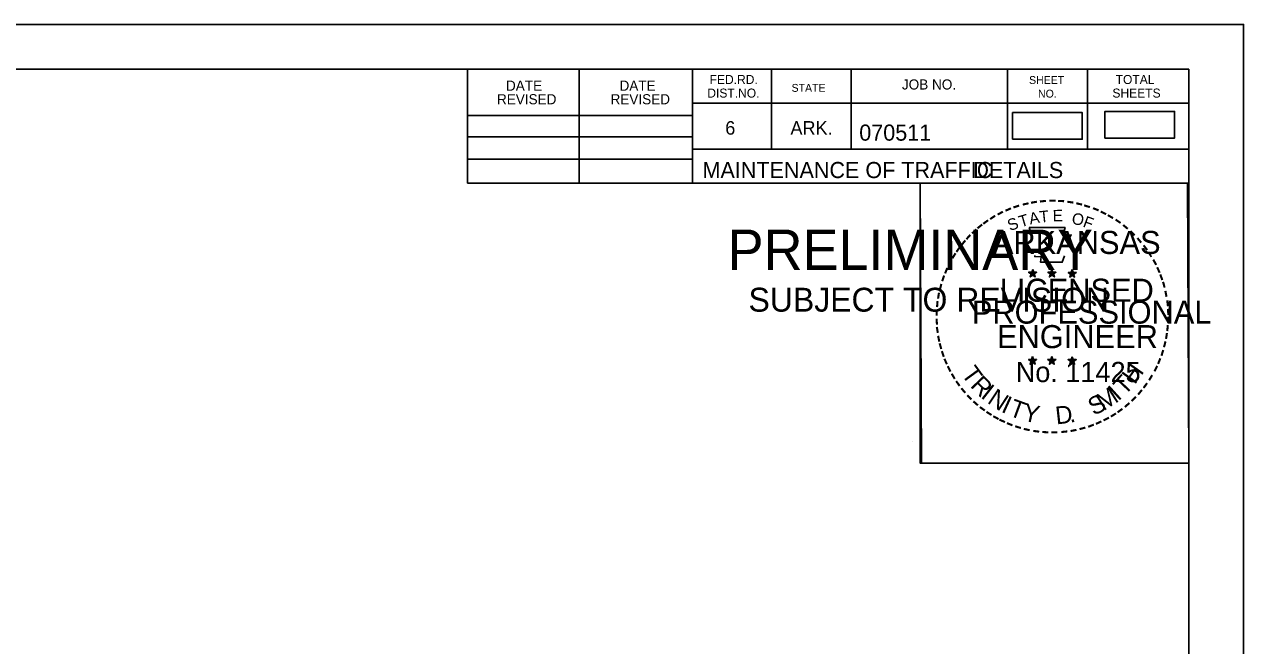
# Model space of a CAD drawing. Extents: x 1398460 to 1408037, y 380768 to 383968.
# Drawn here: x 1403470 to 1403999, y 383698 to 383968 of the extents above; entities that cross this region are included whole.
import ezdxf

# ---------------------------------------------------------------- set-up
doc = ezdxf.new("R2010")
doc.units = 0
for name, color, linetype in [('R_Border', 7, 'Continuous'), ('R_Border PE', 7, 'Continuous'), ('R_Border Prem', 7, 'Continuous'), ('R_Dimension', 7, 'Continuous'), ('R_No Plot', 7, 'Continuous')]:
    doc.layers.add(name, color=color, linetype=linetype)

msp = doc.modelspace()

# ---------------------------------------------------------------- linework, layer by layer
at = {"layer": 'R_Border'}
for p, q in [((1402394.27, 383948.11), (1403975.17, 383948.11)), ((1403661.97, 383898.71), (1403661.97, 383948.11)), ((1403710.37, 383898.71), (1403710.37, 383948.11)), ((1403759.67, 383948.11), (1403759.67, 383898.71)), ((1403793.87, 383948.11), (1403793.87, 383913.41)), ((1403828.57, 383948.11), (1403828.57, 383913.41)), ((1403896.47, 383948.11), (1403896.47, 383913.41)), ((1403931.17, 383948.11), (1403931.17, 383913.41)), ((1403975.17, 382920.81), (1403975.17, 383948.11)), ((1403975.17, 383933.41), (1403759.67, 383933.41)), ((1403975.17, 383933.51), (1403975.17, 383933.51)), ((1403661.97, 383928.01), (1403759.67, 383928.01)), ((1403661.97, 383918.71), (1403759.67, 383918.71)), ((1403661.97, 383909.01), (1403759.67, 383909.01)), ((1403975.17, 383913.41), (1403759.67, 383913.41)), ((1403774.47, 383913.41), (1403975.17, 383913.41)), ((1403975.17, 383898.71), (1403661.97, 383898.71))]:
    msp.add_line(p, q, dxfattribs=at)
at = {"layer": 'R_Border PE'}
for p, q in [((1403907.34, 383861.25), (1403907.13, 383859.99)), ((1403907.34, 383859.43), (1403907.34, 383861.25)), ((1403907.34, 383861.25), (1403907.58, 383860)), ((1403915.69, 383861.25), (1403915.48, 383859.99)), ((1403915.69, 383859.43), (1403915.69, 383861.25)), ((1403915.69, 383861.25), (1403915.93, 383860)), ((1403924.51, 383861.19), (1403924.3, 383859.93)), ((1403924.51, 383859.37), (1403924.51, 383861.19)), ((1403924.51, 383861.19), (1403924.75, 383859.94)), ((1403905.59, 383859.98), (1403907.34, 383859.43)), ((1403905.59, 383859.98), (1403906.86, 383859.76)), ((1403905.59, 383859.98), (1403906.78, 383859.37)), ((1403906.26, 383857.94), (1403907.34, 383859.43)), ((1403906.26, 383857.94), (1403906.89, 383859.16)), ((1403906.26, 383857.94), (1403907.33, 383859.03)), ((1403908.4, 383857.94), (1403907.33, 383859.01)), ((1403909.07, 383859.98), (1403907.34, 383859.43)), ((1403908.4, 383857.94), (1403907.34, 383859.43)), ((1403909.07, 383859.98), (1403907.64, 383859.74)), ((1403908.4, 383857.94), (1403907.72, 383859.4)), ((1403909.07, 383859.98), (1403908.05, 383859.47)), ((1403913.94, 383859.98), (1403915.69, 383859.43)), ((1403913.94, 383859.98), (1403915.21, 383859.76)), ((1403913.94, 383859.98), (1403915.13, 383859.37)), ((1403914.61, 383857.94), (1403915.69, 383859.43)), ((1403914.61, 383857.94), (1403915.24, 383859.16)), ((1403914.61, 383857.94), (1403915.68, 383859.03)), ((1403916.75, 383857.94), (1403915.68, 383859.01)), ((1403917.42, 383859.98), (1403915.69, 383859.43)), ((1403916.75, 383857.94), (1403915.69, 383859.43)), ((1403917.42, 383859.98), (1403915.99, 383859.74)), ((1403916.75, 383857.94), (1403916.07, 383859.4)), ((1403917.42, 383859.98), (1403916.4, 383859.47)), ((1403922.76, 383859.92), (1403924.51, 383859.37)), ((1403922.76, 383859.92), (1403924.03, 383859.7)), ((1403922.76, 383859.92), (1403923.95, 383859.31)), ((1403923.43, 383857.88), (1403924.51, 383859.37)), ((1403923.43, 383857.88), (1403924.06, 383859.1)), ((1403923.43, 383857.88), (1403924.5, 383858.97)), ((1403925.57, 383857.88), (1403924.5, 383858.95)), ((1403926.24, 383859.92), (1403924.51, 383859.37)), ((1403925.57, 383857.88), (1403924.51, 383859.37)), ((1403926.24, 383859.92), (1403924.81, 383859.68)), ((1403925.57, 383857.88), (1403924.89, 383859.34)), ((1403926.24, 383859.92), (1403925.22, 383859.41)), ((1403905.57, 383822.12), (1403907.32, 383821.56)), ((1403905.57, 383822.12), (1403906.84, 383821.89)), ((1403905.57, 383822.12), (1403906.76, 383821.51)), ((1403906.24, 383820.08), (1403907.32, 383821.56)), ((1403906.24, 383820.08), (1403906.87, 383821.3)), ((1403906.24, 383820.08), (1403907.31, 383821.16)), ((1403907.32, 383823.39), (1403907.11, 383822.13)), ((1403908.38, 383820.08), (1403907.31, 383821.15)), ((1403907.32, 383821.56), (1403907.32, 383823.39)), ((1403907.32, 383823.39), (1403907.56, 383822.14)), ((1403909.05, 383822.12), (1403907.32, 383821.56)), ((1403908.38, 383820.08), (1403907.32, 383821.56)), ((1403909.05, 383822.12), (1403907.62, 383821.87)), ((1403908.38, 383820.08), (1403907.7, 383821.53)), ((1403909.05, 383822.12), (1403908.03, 383821.61)), ((1403913.92, 383822.12), (1403915.66, 383821.56)), ((1403913.92, 383822.12), (1403915.18, 383821.89)), ((1403913.92, 383822.12), (1403915.1, 383821.51)), ((1403914.58, 383820.08), (1403915.66, 383821.56)), ((1403914.58, 383820.08), (1403915.21, 383821.3)), ((1403914.58, 383820.08), (1403915.65, 383821.16)), ((1403915.66, 383823.39), (1403915.46, 383822.13)), ((1403916.73, 383820.08), (1403915.65, 383821.15)), ((1403915.66, 383821.56), (1403915.66, 383823.39)), ((1403915.66, 383823.39), (1403915.91, 383822.14)), ((1403917.4, 383822.12), (1403915.66, 383821.56)), ((1403916.73, 383820.08), (1403915.66, 383821.56)), ((1403917.4, 383822.12), (1403915.97, 383821.87)), ((1403916.73, 383820.08), (1403916.04, 383821.53)), ((1403917.4, 383822.12), (1403916.38, 383821.61)), ((1403922.75, 383822.07), (1403924.5, 383821.51)), ((1403922.75, 383822.07), (1403924.02, 383821.84)), ((1403922.75, 383822.07), (1403923.94, 383821.46)), ((1403923.42, 383820.03), (1403924.5, 383821.51)), ((1403923.42, 383820.03), (1403924.05, 383821.25)), ((1403923.42, 383820.03), (1403924.49, 383821.11)), ((1403924.5, 383823.34), (1403924.29, 383822.08)), ((1403925.56, 383820.03), (1403924.49, 383821.1)), ((1403924.5, 383821.51), (1403924.5, 383823.34)), ((1403924.5, 383823.34), (1403924.74, 383822.09)), ((1403926.23, 383822.07), (1403924.5, 383821.51)), ((1403925.56, 383820.03), (1403924.5, 383821.51)), ((1403926.23, 383822.07), (1403924.8, 383821.82)), ((1403925.56, 383820.03), (1403924.88, 383821.48)), ((1403926.23, 383822.07), (1403925.21, 383821.56))]:
    msp.add_line(p, q, dxfattribs=at)
for points in [[(1403905.8, 383879.37), (1403907.14, 383875.24)], [(1403923.35, 383874.76), (1403924.06, 383876.18), (1403920.64, 383876.06), (1403921.38, 383879.37), (1403905.8, 383879.37)], [(1403908.26, 383867.26), (1403908.26, 383866.82), (1403911.07, 383866.73), (1403910.8, 383864.36), (1403920.15, 383864.36), (1403921.16, 383867.04)], [(1403907.34, 383861.25), (1403908.4, 383857.94), (1403905.59, 383859.98), (1403909.07, 383859.98), (1403906.26, 383857.94), (1403907.34, 383861.25)], [(1403915.69, 383861.25), (1403916.75, 383857.94), (1403913.94, 383859.98), (1403917.42, 383859.98), (1403914.61, 383857.94), (1403915.69, 383861.25)], [(1403924.51, 383861.19), (1403925.57, 383857.88), (1403922.76, 383859.92), (1403926.24, 383859.92), (1403923.43, 383857.88), (1403924.51, 383861.19)], [(1403907.32, 383823.39), (1403908.38, 383820.08), (1403905.57, 383822.12), (1403909.05, 383822.12), (1403906.24, 383820.08), (1403907.32, 383823.39)], [(1403915.66, 383823.39), (1403916.73, 383820.08), (1403913.92, 383822.12), (1403917.4, 383822.12), (1403914.58, 383820.08), (1403915.66, 383823.39)], [(1403924.5, 383823.34), (1403925.56, 383820.03), (1403922.75, 383822.07), (1403926.23, 383822.07), (1403923.42, 383820.03), (1403924.5, 383823.34)]]:
    msp.add_lwpolyline(points, dxfattribs=at)
for centre, radius in [((1403907.33, 383859.42), 0.861), ((1403907.33, 383859.42), 0.723), ((1403907.33, 383859.42), 0.579), ((1403907.33, 383859.42), 0.495), ((1403907.33, 383859.42), 0.374), ((1403907.33, 383859.42), 0.248), ((1403907.33, 383859.42), 0.148), ((1403915.68, 383859.42), 0.861), ((1403915.68, 383859.42), 0.723), ((1403915.68, 383859.42), 0.579), ((1403915.68, 383859.42), 0.495), ((1403915.68, 383859.42), 0.374), ((1403915.68, 383859.42), 0.248), ((1403915.68, 383859.42), 0.148), ((1403924.5, 383859.36), 0.861), ((1403924.5, 383859.36), 0.723), ((1403924.5, 383859.36), 0.579), ((1403924.5, 383859.36), 0.495), ((1403924.5, 383859.36), 0.374), ((1403924.5, 383859.36), 0.248), ((1403924.5, 383859.36), 0.148), ((1403907.31, 383821.56), 0.861), ((1403907.31, 383821.56), 0.723), ((1403907.31, 383821.56), 0.579), ((1403907.31, 383821.56), 0.495), ((1403907.31, 383821.56), 0.374), ((1403907.31, 383821.56), 0.248), ((1403907.31, 383821.56), 0.148), ((1403915.66, 383821.56), 0.861), ((1403915.66, 383821.56), 0.723), ((1403915.66, 383821.56), 0.579), ((1403915.66, 383821.56), 0.495), ((1403915.66, 383821.56), 0.374), ((1403915.66, 383821.56), 0.248), ((1403915.66, 383821.56), 0.148), ((1403924.49, 383821.51), 0.861), ((1403924.49, 383821.51), 0.723), ((1403924.49, 383821.51), 0.579), ((1403924.49, 383821.51), 0.495), ((1403924.49, 383821.51), 0.374), ((1403924.49, 383821.51), 0.248), ((1403924.49, 383821.51), 0.148)]:
    msp.add_circle(centre, radius, dxfattribs=at)
at = {"layer": 'R_Dimension'}
for points in [[(1403898.59, 383917.72), (1403928.86, 383917.72), (1403928.86, 383929.28), (1403898.59, 383929.28)], [(1403938.68, 383918.22), (1403968.95, 383918.22), (1403968.95, 383929.77), (1403938.68, 383929.77)]]:
    msp.add_lwpolyline(points, close=True, dxfattribs=at)
at = {"layer": 'R_No Plot'}
for p, q in [((1402332.26, 383967.58), (1403998.93, 383967.58)), ((1403855.34, 383786.43), (1403855.34, 383786.43))]:
    msp.add_line(p, q, dxfattribs=at)
for points in [[(1402332.23, 383967.58), (1403998.93, 383967.58), (1403998.93, 382900.89), (1402332.23, 382900.89)], [(1403563.87, 383948.11), (1403661.97, 383948.11), (1403661.97, 383898.71), (1403742.53, 383898.71), (1403858.52, 383898.71), (1403858.52, 383777.04), (1403975.17, 383777.04), (1403975.17, 382920.81), (1402394.27, 382920.81), (1402394.27, 383948.11)], [(1403858.52, 383898.71), (1403974.56, 383898.71), (1403975.17, 383777.04), (1403859.13, 383777.04)]]:
    msp.add_lwpolyline(points, close=True, dxfattribs=at)

# ---------------------------------------------------------------- texts
at = {"layer": 'R_Border'}
for s, height, p in [('DATE', 4.396, (1403678.66, 383938.79)), ('DATE', 4.396, (1403727.96, 383938.79)), ('FED.RD.', 3.91, (1403767.07, 383941.71)), ('STATE', 3.42, (1403802.67, 383938.31)), ('JOB NO.', 4.396, (1403850.57, 383939.31)), ('SHEET', 3.42, (1403905.77, 383941.71)), ('TOTAL', 3.91, (1403943.37, 383941.71)), ('REVISED', 4.396, (1403674.76, 383932.89)), ('REVISED', 4.396, (1403724.06, 383932.89)), ('DIST.NO.', 3.91, (1403766.07, 383935.81)), ('NO.', 3.42, (1403909.67, 383935.81)), ('SHEETS', 3.91, (1403941.97, 383935.81)), ('6', 5.86, (1403773.87, 383919.71)), ('ARK.', 5.861, (1403802.17, 383919.71)), ('070511', 7, (1403832.05, 383917.1)), ('MAINTENANCE OF TRAFFIC', 7, (1403763.98, 383900.86)), (' DETAILS', 7, (1403878.98, 383900.86))]:
    msp.add_text(s, height=height, dxfattribs=at).set_placement(p)
at = {"layer": 'R_Border PE'}
for s, height, rotation, p in [('-', 8, 24.3072, (1403896.37, 383883.66)), ('-', 8, 19.1761, (1403899.54, 383885.01)), ('-', 8, 13.6302, (1403903.29, 383886.21)), ('-', 8, 10.2193, (1403906.68, 383887.02)), ('-', 8, 5.8968, (1403910.32, 383887.57)), ('-', 8, 0.1862, (1403914.18, 383887.93)), ('-', 8, 357.743, (1403917.8, 383887.87)), ('-', 8, 352.1617, (1403921.52, 383887.59)), ('-', 8, 347.2049, (1403925.11, 383887.02)), ('-', 8, 342.3362, (1403928.29, 383886.24)), ('-', 8, 337.8551, (1403931.96, 383885.13)), ('-', 8, 36.2317, (1403887.33, 383878.25)), ('-', 8, 34.0636, (1403890.22, 383880.23)), ('-', 8, 28.7918, (1403893.2, 383882.08)), ('S', 5, 21.594, (1403897.57, 383877.76)), ('T', 5, 16.4036, (1403902.14, 383879.42)), ('A', 5, 11.2132, (1403906.27, 383880.67)), ('T', 5, 6.0228, (1403910.52, 383881.5)), ('E', 5, 0.8323, (1403916.04, 383882.05)), ('O', 5, 350.4515, (1403924.06, 383881)), ('F', 5, 340.0707, (1403928.83, 383879.86)), ('-', 8, 334.1211, (1403935.12, 383883.77)), ('-', 8, 329.6409, (1403938.01, 383882.36)), ('-', 8, 325.8627, (1403941.23, 383880.55)), ('-', 8, 42.9622, (1403882.78, 383874.28)), ('-', 8, 38.9507, (1403884.95, 383876.36)), ('-', 8, 320.5297, (1403944.28, 383878.42)), ('-', 8, 315.5786, (1403947.27, 383875.98)), ('-', 8, 50.6142, (1403878.53, 383869.46)), ('-', 8, 48.4231, (1403880.54, 383871.89)), ('-', 8, 309.8797, (1403950.12, 383873.23)), ('-', 8, 306.6522, (1403952.74, 383870.22)), ('-', 8, 58.0706, (1403874.84, 383863.99)), ('-', 8, 54.2325, (1403876.46, 383866.62)), ('-', 7, 303.6753, (1403955.17, 383867.38)), ('-', 8, 67.7743, (1403871.98, 383857.86)), ('-', 8, 62.8713, (1403873.27, 383860.92)), ('-', 8, 299.6684, (1403956.77, 383864.35)), ('-', 8, 294.6628, (1403958.39, 383861.29)), ('-', 8, 72.3945, (1403870.88, 383854.71)), ('-', 8, 290.5728, (1403959.67, 383858.4)), ('-', 8, 285.1233, (1403960.84, 383855.5)), ('-', 8, 81.2013, (1403869.24, 383847.58)), ('-', 8, 75.461, (1403869.9, 383851.14)), ('-', 8, 280.5493, (1403961.84, 383851.79)), ('-', 8, 85.1863, (1403868.86, 383844.12)), ('-', 8, 276.5962, (1403962.65, 383847.95)), ('-', 8, 89.0622, (1403868.73, 383840.62)), ('-', 8, 274.3301, (1403962.95, 383844.34)), ('-', 8, 269.9407, (1403963.12, 383841.18)), ('-', 8, 94.1959, (1403868.91, 383836.99)), ('-', 8, 98.9479, (1403869.27, 383833.66)), ('-', 8, 263.5172, (1403963.03, 383837.85)), ('-', 8, 101.7149, (1403869.94, 383829.99)), ('-', 8, 255.7626, (1403962.12, 383831.19)), ('-', 8, 260.9953, (1403962.67, 383834.58)), ('-', 8, 105.4578, (1403870.75, 383827.02)), ('-', 8, 109.0874, (1403871.83, 383823.86)), ('-', 8, 252.8681, (1403961.22, 383827.59)), ('-', 8, 114.0643, (1403873.1, 383820.88)), ('-', 8, 115.7289, (1403874.62, 383817.79)), ('T', 7.7, 306.0406, (1403876.11, 383815.75)), ('H', 7.7, 54.6088, (1403951.71, 383810.93)), ('-', 8, 244.6197, (1403958.79, 383821.08)), ('-', 8, 247.8887, (1403960.1, 383824.23)), ('-', 8, 120.4471, (1403876.41, 383814.86)), ('R', 7.7, 314.005, (1403879.93, 383810.51)), ('T', 7.7, 46.6444, (1403947.27, 383806.22)), ('-', 8, 239.0712, (1403956.82, 383817.32)), ('-', 8, 125.8934, (1403878.42, 383812.06)), ('-', 8, 130.7181, (1403880.73, 383809.3)), ('I', 7.7, 321.9694, (1403884.43, 383805.85)), ('N', 7.7, 326.5002, (1403887.26, 383803.5)), ('M', 7.7, 32.6563, (1403938.04, 383799.59)), ('I', 7.7, 42.1136, (1403944.46, 383803.83)), ('-', 8, 231.2538, (1403952.66, 383811.23)), ('-', 8, 233.8452, (1403954.81, 383814.06)), ('-', 8, 134.2238, (1403883.32, 383806.57)), ('-', 8, 138.9338, (1403885.94, 383804.25)), ('I', 7.7, 335.3603, (1403893.31, 383799.57)), ('T', 7.7, 339.8912, (1403896.61, 383797.93)), ('Y', 7.7, 347.8556, (1403902.7, 383795.7)), ('S', 7.7, 26.9312, (1403933.84, 383797.56)), ('-', 8, 221.0851, (1403947.66, 383805.86)), ('-', 8, 225.7653, (1403950.27, 383808.41)), ('-', 8, 144.6463, (1403888.72, 383802.22)), ('-', 8, 148.0898, (1403891.53, 383800.37)), ('-', 8, 151.5704, (1403894.42, 383798.74)), ('D', 7.7, 6.3969, (1403917.62, 383793.91)), ('-', 8, 212.2491, (1403942.24, 383801.57)), ('-', 8, 215.7363, (1403944.91, 383803.5)), ('-', 8, 154.6002, (1403897.03, 383797.51)), ('-', 8, 158.5612, (1403900.15, 383796.24)), ('-', 8, 162.7983, (1403903.59, 383795.17)), ('-', 8, 167.5555, (1403907.16, 383794.35)), ('.', 7.7, 13.7642, (1403923.58, 383794.55)), ('-', 8, 195.4743, (1403929.85, 383795.67)), ('-', 8, 200.7184, (1403933.24, 383796.88)), ('-', 8, 204.2516, (1403936.33, 383798.24)), ('-', 8, 207.3568, (1403939.45, 383799.84)), ('-', 8, 173.1155, (1403911.02, 383793.8)), ('-', 8, 176.5183, (1403914.76, 383793.54)), ('-', 8, 181.5918, (1403918.48, 383793.63)), ('-', 8, 185.8167, (1403922.53, 383794.01)), ('-', 8, 191.2858, (1403926.21, 383794.67))]:
    msp.add_text(s, height=height, rotation=rotation, dxfattribs=at).set_placement(p)
for s, height, p in [('ARKANSAS', 10, (1403890.06, 383867.93)), ('LICENSED', 10, (1403893.05, 383847.19)), ('DWB', 0.05, (1403907.27, 383859.4)), ('DWB', 0.05, (1403915.62, 383859.4)), ('DWB', 0.05, (1403924.44, 383859.35)), ('PROFESSIONAL', 10, (1403880.93, 383837.67)), ('ENGINEER', 10, (1403891.87, 383827.04)), ('No. 11425', 8.785, (1403900, 383812.29)), ('DWB', 0.05, (1403907.25, 383821.54)), ('DWB', 0.05, (1403915.6, 383821.54)), ('DWB', 0.05, (1403924.43, 383821.49))]:
    msp.add_text(s, height=height, dxfattribs=at).set_placement(p)
at = {"layer": 'R_Border Prem'}
for s, height, p in [('PRELIMINARY', 17.5, (1403774.92, 383861.02)), ('DWB', 0.05, (1403778.66, 383870.27)), ('SUBJECT TO REVISION', 10.3756, (1403783.97, 383842.88))]:
    msp.add_text(s, height=height, dxfattribs=at).set_placement(p)

doc.saveas('drawing.dxf')
